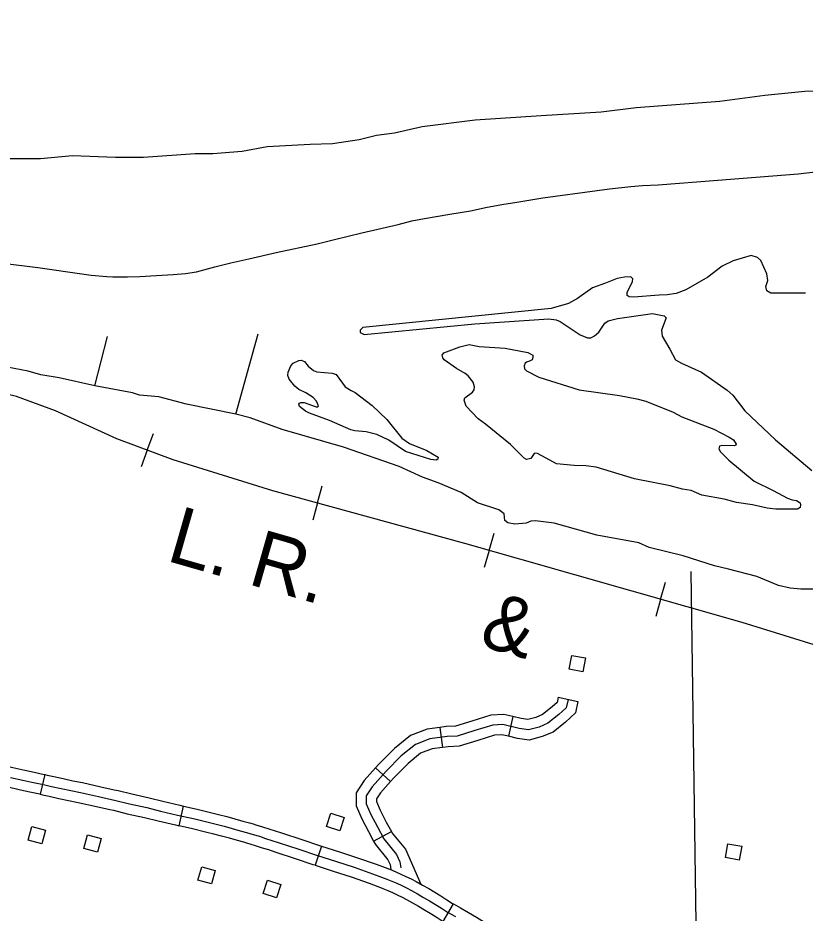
# Model space of a CAD drawing. Extents: x -19 to 366, y -4 to 359.
# Drawn here: x 140.457 to 141.561, y 204.187 to 205.442 of the extents above; entities that cross this region are included whole.
import ezdxf

# ---------------------------------------------------------------- set-up
doc = ezdxf.new("R2010")
doc.units = 0
for name, color, linetype in [('Level 2', 7, 'Continuous'), ('Level 31', 7, 'Continuous'), ('Level 32', 7, 'Continuous'), ('Level 40', 7, 'Continuous'), ('Level 5', 7, 'Continuous'), ('Level 56', 7, 'Continuous'), ('Level 60', 7, 'Continuous'), ('Level 9', 7, 'Continuous')]:
    doc.layers.add(name, color=color, linetype=linetype)

msp = doc.modelspace()

# ---------------------------------------------------------------- linework, layer by layer
at = {"layer": 'Level 2'}
msp.add_lwpolyline([(140.4358, 205.0985), (140.485, 205.0923), (140.5467, 205.0832), (140.5601, 205.0817), (140.5819, 205.0796), (140.5904, 205.0793), (140.6109, 205.0791), (140.6283, 205.0796), (140.6749, 205.0825), (140.692, 205.0837), (140.7076, 205.0863), (140.7332, 205.0931), (140.7557, 205.0988), (140.7808, 205.1046), (140.8192, 205.1133), (140.8767, 205.1255), (140.9011, 205.1317), (140.9394, 205.141), (140.9907, 205.1527), (141.0097, 205.1576), (141.0275, 205.161), (141.0628, 205.167), (141.0918, 205.1719), (141.1154, 205.1768), (141.1389, 205.1812), (141.154, 205.1836), (141.1936, 205.1898), (141.2695, 205.2004), (141.2869, 205.2028), (141.3167, 205.2059), (141.333, 205.2072), (141.3551, 205.2083), (141.439, 205.2146), (141.5515, 205.2236), (141.661, 205.2362)], dxfattribs=at)
at = {"layer": 'Level 31'}
for p, q in [((140.4947, 204.3812), (140.4884, 204.3535)), ((140.6834, 204.3092), (140.6896, 204.3369)), ((140.6896, 204.3369), (140.6896, 204.3369)), ((140.8828, 204.2808), (140.8741, 204.2538)), ((141.0537, 204.1751), (141.0679, 204.1997))]:
    msp.add_line(p, q, dxfattribs=at)
for points in [[(140.3951, 204.4009), (140.3985, 204.4005), (140.4042, 204.3998), (140.4099, 204.399), (140.4156, 204.3981), (140.4213, 204.3971), (140.427, 204.3961), (140.4363, 204.3941), (140.4498, 204.391), (140.467, 204.3871), (140.4797, 204.3843), (140.4938, 204.3814), (140.4947, 204.3812)], [(140.4884, 204.3535), (140.4878, 204.3536), (140.4738, 204.3565), (140.4608, 204.3593), (140.4435, 204.3633), (140.4302, 204.3664), (140.4215, 204.3682), (140.4163, 204.3692), (140.411, 204.3701), (140.4057, 204.3709), (140.4004, 204.3717), (140.3951, 204.3723), (140.3919, 204.3727)], [(140.4467, 204.3771), (140.4639, 204.3732), (140.4768, 204.3704), (140.4908, 204.3675), (140.4949, 204.3666), (140.5042, 204.3645), (140.5177, 204.3615), (140.5312, 204.3586), (140.5447, 204.3559), (140.5703, 204.3502), (140.5946, 204.3448), (140.6138, 204.3401), (140.6378, 204.3347), (140.6571, 204.3299), (140.6812, 204.3242), (140.7052, 204.3188), (140.7238, 204.3142), (140.7352, 204.3114), (140.7465, 204.3085), (140.7577, 204.3054), (140.769, 204.3023), (140.7779, 204.2998), (140.7869, 204.2972)], [(140.4947, 204.3812), (140.498, 204.3804), (140.5073, 204.3783), (140.5207, 204.3754), (140.5341, 204.3725), (140.5476, 204.3698), (140.5733, 204.3641), (140.5923, 204.3599)], [(140.5923, 204.3599), (140.5978, 204.3586), (140.617, 204.3539), (140.6411, 204.3485), (140.6604, 204.3437), (140.6844, 204.3381), (140.6896, 204.3369)], [(140.4884, 204.3535), (140.4917, 204.3527), (140.5011, 204.3506), (140.5147, 204.3476), (140.5283, 204.3447), (140.5417, 204.342), (140.5672, 204.3364), (140.5861, 204.3321)], [(140.6896, 204.3369), (140.7084, 204.3326), (140.7273, 204.328), (140.7387, 204.3252), (140.7501, 204.3222), (140.7615, 204.3191), (140.7728, 204.3159), (140.7818, 204.3134), (140.7873, 204.3118)], [(140.5861, 204.3321), (140.5913, 204.331), (140.6105, 204.3262), (140.6346, 204.3208), (140.6538, 204.3161), (140.678, 204.3104), (140.6834, 204.3092)], [(140.7794, 204.2845), (140.7741, 204.2861), (140.7651, 204.2886), (140.754, 204.2917), (140.7428, 204.2947), (140.7317, 204.2976), (140.7204, 204.3004), (140.7019, 204.305), (140.6834, 204.3092)], [(140.7873, 204.3118), (140.7909, 204.3108), (140.8, 204.308), (140.809, 204.3052), (140.818, 204.3022), (140.8268, 204.2992), (140.8555, 204.2898), (140.8802, 204.2817), (140.8828, 204.2808)], [(140.7869, 204.2972), (140.7958, 204.2945), (140.8046, 204.2916), (140.8135, 204.2887), (140.8223, 204.2857), (140.8511, 204.2763), (140.8758, 204.2681), (140.9038, 204.2591), (140.929, 204.251), (140.9547, 204.2421), (140.9673, 204.2374), (140.9744, 204.2346), (140.9814, 204.2317), (140.9884, 204.2286), (140.9954, 204.2254), (141.0022, 204.2221), (141.009, 204.2186), (141.0176, 204.2138), (141.0261, 204.2088), (141.0345, 204.2038), (141.0429, 204.1987), (141.0512, 204.1935), (141.0595, 204.1882), (141.0707, 204.1818)], [(140.8741, 204.2538), (140.8714, 204.2546), (140.8466, 204.2629), (140.8178, 204.2722), (140.809, 204.2753), (140.8003, 204.2781), (140.7916, 204.2809), (140.7828, 204.2835), (140.7794, 204.2845)], [(140.8828, 204.2808), (140.9081, 204.2727), (140.9335, 204.2645), (140.9595, 204.2555), (140.9724, 204.2507), (140.9784, 204.2483)], [(140.8741, 204.2538), (140.8994, 204.2456), (140.9245, 204.2375), (140.9499, 204.2287), (140.9622, 204.2242), (140.9679, 204.2219)], [(140.9784, 204.2483), (140.9798, 204.2478), (140.987, 204.2447), (140.9943, 204.2415), (141.0014, 204.2382), (141.0085, 204.2348), (141.0158, 204.2311), (141.0246, 204.2261), (141.0333, 204.2211), (141.0418, 204.216), (141.0504, 204.2108), (141.0588, 204.2055), (141.0668, 204.2004), (141.0679, 204.1997)], [(140.9679, 204.2219), (140.969, 204.2215), (140.9758, 204.2186), (140.9826, 204.2156), (140.9893, 204.2125), (140.9959, 204.2093), (141.0023, 204.2061), (141.0105, 204.2014), (141.0189, 204.1966), (141.0272, 204.1916), (141.0354, 204.1866), (141.0436, 204.1815), (141.0521, 204.1761), (141.0537, 204.1751)], [(141.0679, 204.1997), (141.0778, 204.1941), (141.0891, 204.1875), (141.1003, 204.1809), (141.1114, 204.1742), (141.1164, 204.1712), (141.1214, 204.1684), (141.1264, 204.1657), (141.1315, 204.1631), (141.1367, 204.1606), (141.1418, 204.1582), (141.1471, 204.1559), (141.1517, 204.154), (141.1525, 204.1538)]]:
    msp.add_lwpolyline(points, dxfattribs=at)
at = {"layer": 'Level 32'}
for p, q in [((141.2149, 204.4896), (141.2426, 204.4834)), ((141.1512, 204.4625), (141.1451, 204.4348)), ((141.049, 204.4473), (141.0527, 204.4191)), ((140.9585, 204.3904), (140.9798, 204.3716)), ((140.956, 204.2878), (140.981, 204.3012))]:
    msp.add_line(p, q, dxfattribs=at)
for points in [[(141.2288, 204.4865), (141.2262, 204.4749), (141.2159, 204.4652), (141.2004, 204.453), (141.1882, 204.4478), (141.1733, 204.444), (141.1604, 204.4459), (141.1372, 204.4511), (141.1231, 204.4504), (141.0979, 204.4427), (141.0734, 204.4349), (141.0592, 204.4343), (141.0348, 204.4311), (141.0148, 204.4233), (140.9948, 204.4072), (140.9735, 204.3859), (140.9542, 204.364), (140.9458, 204.3511), (140.9458, 204.3401), (140.9523, 204.3253), (140.9613, 204.3079), (140.9703, 204.2911), (140.9883, 204.2692), (140.9929, 204.2589), (140.994, 204.2502)], [(141.2149, 204.4896), (141.2133, 204.4823), (141.2066, 204.476), (141.1931, 204.4653), (141.1836, 204.4613), (141.1726, 204.4584), (141.163, 204.4599), (141.1512, 204.4625)], [(141.2426, 204.4834), (141.2391, 204.4676), (141.2252, 204.4545), (141.2077, 204.4406), (141.1927, 204.4343), (141.1741, 204.4295), (141.1578, 204.4319), (141.1451, 204.4348)], [(141.1512, 204.4625), (141.1385, 204.4653), (141.1206, 204.4645), (141.0937, 204.4562), (141.0709, 204.449), (141.058, 204.4484), (141.049, 204.4473)], [(141.049, 204.4473), (141.0312, 204.4449), (141.0076, 204.4358), (140.9853, 204.4178), (140.9632, 204.3956), (140.9585, 204.3904)], [(141.1451, 204.4348), (141.136, 204.4368), (141.1255, 204.4363), (141.1021, 204.4291), (141.0759, 204.4208), (141.0605, 204.4201), (141.0527, 204.4191)], [(141.0527, 204.4191), (141.0383, 204.4172), (141.022, 204.4109), (141.0043, 204.3966), (140.9839, 204.3762), (140.9798, 204.3716)], [(140.9585, 204.3904), (140.9428, 204.3726), (140.9316, 204.3553), (140.9316, 204.3372), (140.9394, 204.3192), (140.9487, 204.3013), (140.956, 204.2878)], [(140.9798, 204.3716), (140.9655, 204.3554), (140.96, 204.3469), (140.96, 204.3431), (140.9651, 204.3314), (140.9738, 204.3145), (140.981, 204.3012)], [(140.981, 204.3012), (140.9822, 204.2991), (141.0006, 204.2767), (141.0221, 204.2275)], [(140.956, 204.2878), (140.9585, 204.2832), (140.9761, 204.2617), (140.9791, 204.255), (140.98, 204.2478)]]:
    msp.add_lwpolyline(points, dxfattribs=at)
at = {"layer": 'Level 40'}
for p, q in [((140.6386, 204.8362), (140.6473, 204.8596)), ((140.6386, 204.8362), (140.6298, 204.8127)), ((140.8772, 204.762), (140.8839, 204.7861)), ((140.8772, 204.762), (140.8706, 204.7379)), ((141.1182, 204.6954), (141.1251, 204.7195)), ((141.1182, 204.6954), (141.1113, 204.6714)), ((141.3586, 204.6268), (141.3655, 204.6508)), ((141.3586, 204.6268), (141.3517, 204.6028))]:
    msp.add_line(p, q, dxfattribs=at)
for points in [[(140.6749, 204.8226), (140.5957, 204.8522), (140.51, 204.8913), (140.4551, 204.9114), (140.3969, 204.9252), (140.2796, 204.9495), (140.157, 204.9728), (140.0185, 205.0024), (139.9435, 205.014), (139.8822, 205.0204), (139.8177, 205.0204), (139.768, 205.0161), (139.731, 205.0161), (139.6962, 205.0214), (139.6314, 205.0435), (139.5747, 205.0673), (139.5398, 205.0785), (139.5146, 205.0841), (139.4082, 205.1037), (139.3802, 205.109)], [(141.6674, 204.5339), (141.473, 204.5942), (141.084, 204.7052), (140.8145, 204.7792), (140.6749, 204.8226), (140.5957, 204.8522), (140.51, 204.8913), (140.4551, 204.9114), (140.3969, 204.9252), (140.2796, 204.9495), (140.157, 204.9728), (140.0185, 205.0024), (139.9435, 205.014), (139.8822, 205.0204), (139.8177, 205.0204), (139.768, 205.0161), (139.731, 205.0161), (139.6962, 205.0214), (139.6314, 205.0435), (139.5747, 205.0673), (139.5398, 205.0785), (139.5146, 205.0841), (139.4082, 205.1037), (139.3802, 205.109)], [(142.5099, 204.1309), (142.4708, 204.1997), (142.4401, 204.2388), (142.4063, 204.2748), (142.3735, 204.3001), (142.3408, 204.3192), (142.2985, 204.3372), (142.2435, 204.3551), (142.1727, 204.3752), (141.8778, 204.463), (141.6674, 204.5339), (141.473, 204.5942), (141.084, 204.7052), (140.8145, 204.7792), (140.6749, 204.8226)]]:
    msp.add_lwpolyline(points, dxfattribs=at)
at = {"layer": 'Level 5'}
msp.add_lwpolyline([(141.4009, 204.6657), (141.4088, 204.1065)], dxfattribs=at)
at = {"layer": 'Level 56'}
for points in [[(141.2533, 204.5446), (141.2497, 204.5252), (141.2303, 204.5288), (141.2339, 204.5482)], [(140.9149, 204.3207), (140.9087, 204.302), (140.89, 204.3083), (140.8962, 204.327)], [(140.4958, 204.3031), (140.4906, 204.2841), (140.4715, 204.2893), (140.4768, 204.3083)], [(140.574, 204.2913), (140.5687, 204.2722), (140.5497, 204.2775), (140.5549, 204.2965)], [(141.4726, 204.2806), (141.469, 204.2612), (141.4496, 204.2647), (141.4531, 204.2841)], [(140.7339, 204.2467), (140.7287, 204.2277), (140.7096, 204.2329), (140.7149, 204.2519)], [(140.8072, 204.2332), (140.8259, 204.227), (140.8197, 204.2082), (140.8009, 204.2144)]]:
    msp.add_lwpolyline(points, close=True, dxfattribs=at)
at = {"layer": 'Level 60'}
for points in [[(146.7783, 1.697), (146.5788, 10.3131), (146.3785, 18.9294), (146.1776, 27.5458), (145.9759, 36.1624), (145.7736, 44.7791), (145.5705, 53.396), (145.3668, 62.013), (145.1624, 70.6301), (144.9572, 79.2474), (144.7514, 87.8648), (144.5449, 96.4823), (144.3377, 105.1), (144.1299, 113.7179), (143.9213, 122.3359), (143.712, 130.954), (143.5021, 139.5723), (143.2915, 148.1907), (143.0802, 156.8092), (142.8682, 165.4279), (142.6555, 174.0468), (142.4422, 182.6658), (142.2282, 191.2849), (142.0135, 199.9042), (141.7981, 208.5236), (141.582, 217.1432), (141.3653, 225.7629), (141.1479, 234.3828), (140.9298, 243.0028), (140.711, 251.623), (140.4916, 260.2433), (140.2715, 268.8638), (140.0508, 277.4844), (139.8293, 286.1051), (139.6072, 294.726), (139.3845, 303.3471), (139.161, 311.9683), (138.937, 320.5896), (138.7122, 329.2111), (138.4868, 337.8328), (138.2607, 346.4546)], [(0, 198.1326), (7.1014, 198.137), (14.2028, 198.1503), (21.3042, 198.1724), (28.4055, 198.2034), (35.5068, 198.2433), (42.6081, 198.292), (49.7092, 198.3496), (56.8103, 198.4161), (63.9113, 198.4913), (71.0123, 198.5755), (78.1131, 198.6685), (85.2137, 198.7704), (92.3143, 198.8811), (99.4147, 199.0007), (106.5149, 199.1291), (113.615, 199.2664), (120.7149, 199.4126), (127.8146, 199.5676), (134.9141, 199.7315), (142.0135, 199.9042), (149.1125, 200.0858), (156.2114, 200.2762), (163.31, 200.4755), (170.4084, 200.6837), (177.5065, 200.9007), (184.6043, 201.1265), (191.7018, 201.3612), (198.799, 201.6048), (205.896, 201.8572), (212.9926, 202.1185), (220.0888, 202.3886), (227.1848, 202.6676), (234.2803, 202.9554), (241.3755, 203.2521), (248.4704, 203.5576), (255.5648, 203.872), (262.6589, 204.1952), (269.7525, 204.5273), (276.8457, 204.8682), (283.9385, 205.218), (291.0309, 205.5766), (298.1228, 205.9441), (305.2142, 206.3204), (312.3051, 206.7056), (319.3956, 207.0996), (326.4856, 207.5024), (333.5751, 207.9141), (340.664, 208.3347)]]:
    msp.add_spline(points, degree=3, dxfattribs=at)
at = {"layer": 'Level 9'}
for points in [[(141.6363, 205.3403), (141.5607, 205.3392), (141.5046, 205.3336), (141.4415, 205.3253), (141.3241, 205.3161), (141.2754, 205.3101), (141.191, 205.3052), (141.0985, 205.299), (141.0241, 205.2896), (140.9855, 205.2809), (140.96, 205.2773), (140.9356, 205.2712), (140.8986, 205.2658), (140.8672, 205.265), (140.8068, 205.2617), (140.7716, 205.255), (140.7307, 205.2515), (140.7057, 205.2515), (140.6333, 205.2467), (140.594, 205.2467), (140.5339, 205.2489), (140.4887, 205.2449), (140.4427, 205.2447)], [(141.5618, 205.0561), (141.5133, 205.0562), (141.5075, 205.0598), (141.5064, 205.0657), (141.509, 205.074), (141.5078, 205.0834), (141.4994, 205.1022), (141.4944, 205.1064), (141.4854, 205.109), (141.4604, 205.1018), (141.4449, 205.0941), (141.4249, 205.0789), (141.394, 205.0611), (141.3805, 205.0557), (141.3676, 205.0538), (141.3567, 205.0537), (141.3207, 205.0507), (141.3146, 205.0513), (141.3119, 205.0531), (141.3118, 205.0571), (141.3193, 205.0729), (141.3196, 205.0766), (141.3169, 205.0791), (141.308, 205.0787), (141.2978, 205.0769), (141.2811, 205.0701), (141.2629, 205.064), (141.242, 205.0486), (141.2293, 205.0418), (141.2052, 205.0348), (140.9411, 205.0082), (140.937, 205.0046), (140.9371, 205.001), (140.9427, 204.9985), (141.0978, 205.0135), (141.2017, 205.0204), (141.2119, 205.0188), (141.2177, 205.0167), (141.2457, 204.9977), (141.2559, 204.9935), (141.2608, 204.9938), (141.266, 204.9966), (141.272, 205.0017)], [(141.272, 205.0017), (141.2805, 205.0142), (141.2851, 205.0177), (141.2983, 205.0208), (141.3472, 205.0279), (141.3638, 205.0246), (141.3665, 205.0215), (141.36, 205.0045), (141.3606, 204.9962), (141.3716, 204.9777), (141.3796, 204.9627), (141.3877, 204.958), (141.4159, 204.9457), (141.4519, 204.9201), (141.4599, 204.9133), (141.4767, 204.8912), (141.5197, 204.8506), (141.5708, 204.8078)], [(140.7629, 204.8865), (140.7939, 204.9993)], [(140.5652, 204.9264), (140.5827, 204.9957)], [(141.3218, 204.7959), (141.2683, 204.8122), (141.2538, 204.8141), (141.2373, 204.8145), (141.2128, 204.8169), (141.1981, 204.825), (141.186, 204.8315), (141.1835, 204.832), (141.1811, 204.8313), (141.1764, 204.8245), (141.1703, 204.823), (141.1671, 204.8248), (141.1481, 204.8439), (141.1132, 204.8727), (141.1025, 204.8802), (141.0861, 204.898), (141.083, 204.9064), (141.084, 204.9093), (141.0946, 204.9174), (141.0971, 204.9205), (141.0976, 204.9247), (141.0955, 204.9313), (141.0888, 204.9404), (141.0847, 204.9437), (141.0724, 204.9506), (141.0548, 204.963), (141.053, 204.9654), (141.0523, 204.9692), (141.0547, 204.9727), (141.0772, 204.981), (141.0903, 204.9842), (141.1039, 204.9816), (141.1407, 204.9791), (141.1722, 204.9729), (141.1793, 204.9694), (141.1796, 204.9663), (141.1783, 204.963), (141.1748, 204.9607), (141.1705, 204.9596), (141.1684, 204.958), (141.1672, 204.9542), (141.1679, 204.9502), (141.1705, 204.9476), (141.188, 204.9384), (141.2442, 204.9207), (141.3009, 204.9128)], [(140.9748, 204.8791), (140.9957, 204.8527), (141.0065, 204.8456), (141.0309, 204.8357), (141.0467, 204.8262), (141.046, 204.8237), (141.0438, 204.8222), (141.0365, 204.8229), (141.001, 204.8344), (140.9772, 204.8503), (140.9605, 204.8581), (140.9456, 204.8619), (140.9296, 204.8633), (140.9239, 204.8648), (140.8943, 204.8779), (140.8661, 204.8879), (140.8606, 204.8908), (140.8522, 204.8972), (140.851, 204.9004), (140.8519, 204.9019), (140.8541, 204.9029), (140.8585, 204.9029), (140.8755, 204.8969), (140.8776, 204.8971), (140.8789, 204.8983), (140.8761, 204.9047), (140.8714, 204.9099), (140.8611, 204.9163), (140.8511, 204.9213), (140.8455, 204.9257), (140.8374, 204.9359), (140.8356, 204.941), (140.836, 204.9454), (140.8401, 204.9546), (140.8434, 204.9579), (140.8513, 204.9618), (140.8543, 204.9623), (140.8593, 204.9603), (140.8644, 204.954), (140.8716, 204.9479), (140.8762, 204.9462), (140.8978, 204.9443), (140.9034, 204.9424), (140.9162, 204.9251), (140.9247, 204.9198), (140.9303, 204.9168)], [(140.7629, 204.8865), (140.6937, 204.9005), (140.6547, 204.9107), (140.6279, 204.9134), (140.618, 204.9163), (140.5652, 204.9264), (140.515, 204.9376), (140.4893, 204.9418), (140.4714, 204.9468), (140.4317, 204.9542)], [(140.9303, 204.9168), (140.954, 204.8986), (140.9748, 204.8791)], [(141.3009, 204.9128), (141.3251, 204.908), (141.3377, 204.9046), (141.3763, 204.8894), (141.3886, 204.8829), (141.4333, 204.8656), (141.4548, 204.8542), (141.461, 204.8506), (141.4648, 204.8446), (141.4643, 204.8429), (141.4618, 204.8421), (141.4445, 204.8427), (141.441, 204.8416), (141.4405, 204.838), (141.4424, 204.8337), (141.4541, 204.8219), (141.4898, 204.7927), (141.5167, 204.7796), (141.5364, 204.7688), (141.5431, 204.7665), (141.549, 204.7657), (141.5544, 204.7623), (141.555, 204.7596), (141.5542, 204.7556), (141.5505, 204.7532), (141.5203, 204.7533), (141.508, 204.7548), (141.4876, 204.7593), (141.4651, 204.7629), (141.4477, 204.7675), (141.4163, 204.7732), (141.4017, 204.7793), (141.3893, 204.7814), (141.3721, 204.7862), (141.3218, 204.7959)], [(141.5788, 204.6413), (141.5553, 204.6411), (141.5403, 204.6426), (141.5239, 204.6465), (141.4937, 204.6587), (141.4538, 204.6693), (141.4342, 204.6739), (141.3904, 204.688), (141.3426, 204.6997), (141.3279, 204.706), (141.269, 204.7168), (141.2095, 204.7337), (141.1833, 204.7369), (141.1767, 204.7363), (141.1701, 204.7338), (141.1541, 204.7324), (141.1443, 204.7342), (141.1399, 204.7373), (141.1392, 204.7466), (141.1315, 204.7523), (141.102, 204.7621), (141.079, 204.7768), (141.0464, 204.7901), (141.0246, 204.7982), (140.9917, 204.813), (140.9136, 204.8402), (140.828, 204.8651), (140.7829, 204.8814), (140.7629, 204.8865)]]:
    msp.add_lwpolyline(points, dxfattribs=at)

# ---------------------------------------------------------------- texts
at = {"layer": 'Level 40'}
for s, p in [('L. R.', (140.6634, 204.6816)), ('&', (141.1024, 204.5626))]:
    msp.add_text(s, height=0.08, rotation=343.9823, dxfattribs=at).set_placement(p)

doc.saveas('drawing.dxf')
